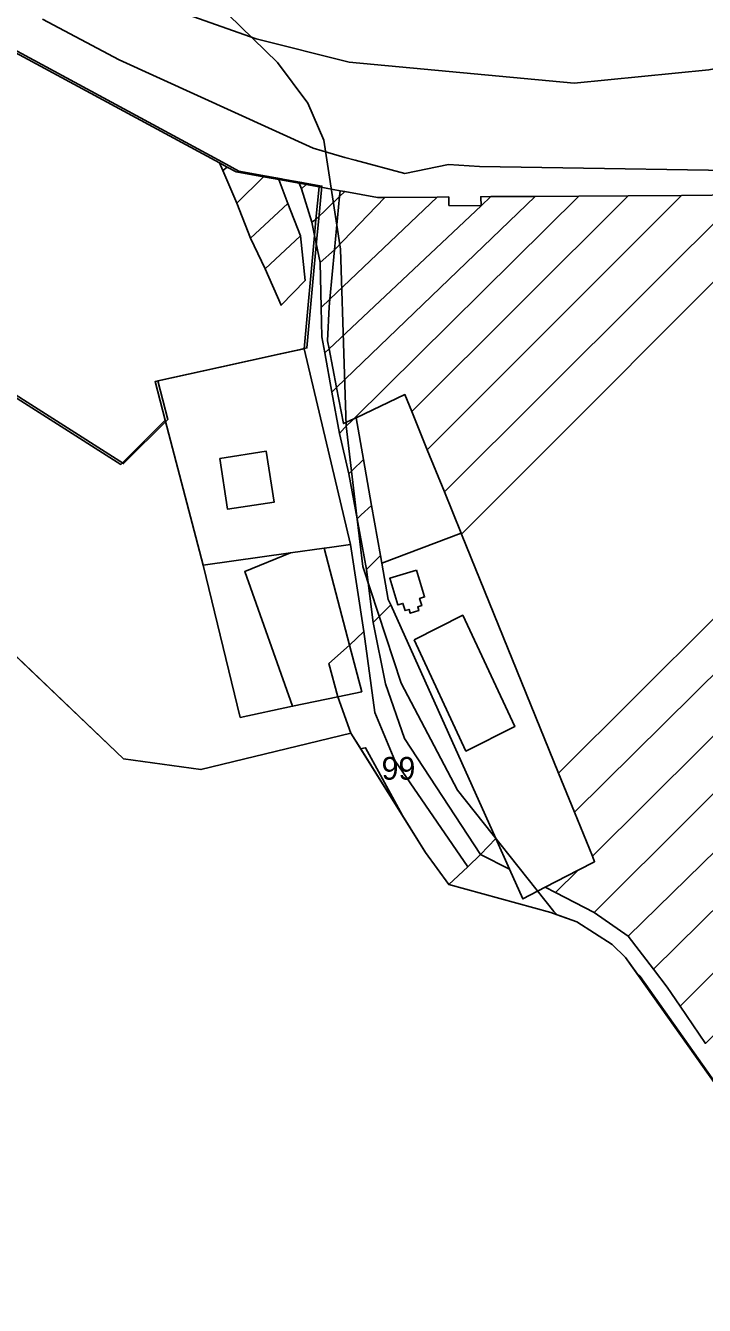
# Model space of a CAD drawing. Extents: x -535894 to -532834, y -1165802 to -1163645.
# Drawn here: x -533412.1 to -533262.6, y -1165186.4 to -1164904.7 of the extents above; entities that cross this region are included whole.
import ezdxf

# ---------------------------------------------------------------- set-up
doc = ezdxf.new("R2010")
doc.units = 0
for name, color, linetype in [('95560013', 7, 'Continuous'), ('95590013', 7, 'Continuous'), ('95600013', 7, 'Continuous'), ('95610013', 7, 'Continuous'), ('95630013', 7, 'Continuous'), ('95640013', 7, 'Continuous'), ('95660013', 7, 'Continuous')]:
    doc.layers.add(name, color=color, linetype=linetype)

msp = doc.modelspace()

# ---------------------------------------------------------------- linework, layer by layer
at = {"layer": '95560013'}
for points in [[(-533149.26, -1164901.65), (-533141.88, -1164917.25), (-533157.58, -1164933.38), (-533260.52, -1165035.2), (-533294.68, -1165069.27), (-533316.06, -1165016.63), (-533241.31, -1164941.86), (-533238.5, -1164941.84), (-533229.28, -1164940.77)], [(-533111.26, -1164912.65), (-533109.04, -1164916.24), (-533107.52, -1164920.92), (-533157.09, -1164970.71), (-533286.88, -1165099.92), (-533295.36, -1165095.55), (-533290.36, -1165090.63), (-533286.76, -1165088.76), (-533287.25, -1165087.56), (-533191.02, -1164991.97), (-533162.21, -1164964.36), (-533147.66, -1164949.6)], [(-533157.58, -1164933.38), (-533152.84, -1164941.12), (-533291.2, -1165077.84), (-533294.68, -1165069.27), (-533260.52, -1165035.2)], [(-533342.95, -1164942.3), (-533341.8, -1164941.18), (-533334.55, -1164942.49), (-533332.94, -1164942.48), (-533344.05, -1164954.01)], [(-533342.83, -1164941), (-533341.8, -1164941.18), (-533342.95, -1164942.3)], [(-533267.6, -1164942.04), (-533254.19, -1164941.95), (-533319.84, -1165007.34), (-533323.61, -1164998.03)], [(-533254.19, -1164941.95), (-533241.31, -1164941.86), (-533316.06, -1165016.63), (-533316.16, -1165016.4), (-533319.84, -1165007.34)], [(-533152.84, -1164941.12), (-533147.66, -1164949.6), (-533162.21, -1164964.36), (-533191.02, -1164991.97), (-533287.25, -1165087.56), (-533291.2, -1165077.84)], [(-533321.4, -1164942.4), (-533318.89, -1164942.38), (-533318.86, -1164944.25), (-533311.76, -1164944.33), (-533345.25, -1164975.83), (-533345.58, -1164974.08), (-533345.23, -1164966.6), (-533345.07, -1164964.92)], [(-533309.61, -1164942.31), (-533299.86, -1164942.25), (-533343.59, -1164984.36), (-533345.25, -1164975.83), (-533311.76, -1164944.33)], [(-533332.94, -1164942.48), (-533321.4, -1164942.4), (-533345.07, -1164964.92), (-533344.05, -1164954.01)], [(-533299.86, -1164942.25), (-533290.22, -1164942.19), (-533339.81, -1164991.22), (-533342.06, -1164992.28), (-533343.59, -1164984.36)], [(-533290.22, -1164942.19), (-533279.34, -1164942.12), (-533327.03, -1164989.6), (-533328.55, -1164985.88), (-533339.3, -1164990.98), (-533339.81, -1164991.22)], [(-533279.34, -1164942.12), (-533267.6, -1164942.04), (-533323.61, -1164998.03), (-533327.03, -1164989.6)], [(-533311.84, -1164942.33), (-533309.61, -1164942.31), (-533311.76, -1164944.33)], [(-533157.09, -1164970.71), (-533151.05, -1164978.13), (-533156.74, -1164983.77), (-533204.88, -1165032.37), (-533279.36, -1165105.17), (-533286.88, -1165099.92)], [(-533156.74, -1164983.77), (-533149.64, -1164990.09), (-533273.82, -1165112.38), (-533279.36, -1165105.17), (-533204.88, -1165032.37)], [(-533327.03, -1164989.6), (-533323.61, -1164998.03), (-533319.84, -1165007.34), (-533316.16, -1165016.4), (-533333.62, -1165022.99), (-533333.91, -1165021.36), (-533335.87, -1165010.29), (-533337.66, -1165000.19), (-533339.3, -1164990.98), (-533328.55, -1164985.88)], [(-533149.64, -1164990.09), (-533146.17, -1164986.67), (-533140.53, -1164993.73), (-533146.54, -1164999.72), (-533267.92, -1165120.55), (-533270.77, -1165116.36), (-533273.82, -1165112.38)], [(-533140.42, -1165007.98), (-533262.35, -1165128.75), (-533267.92, -1165120.55), (-533146.54, -1164999.72)], [(-533353.73, -1165020.77), (-533346.35, -1165019.74), (-533340.73, -1165041.06), (-533345.32, -1165045.1), (-533343.29, -1165052.42), (-533353.28, -1165054.53), (-533363.82, -1165024.85)], [(-533345.15, -1165019.57), (-533340.49, -1165018.91), (-533337.57, -1165038.08), (-533340.73, -1165041.06), (-533346.35, -1165019.74)], [(-533345.32, -1165045.1), (-533340.73, -1165041.06), (-533338.04, -1165051.31), (-533343.29, -1165052.42)], [(-533290.36, -1165090.63), (-533295.36, -1165095.55), (-533297.64, -1165094.39)]]:
    msp.add_lwpolyline(points, close=True, dxfattribs=at)
at = {"layer": '95590013'}
msp.add_lwpolyline([(-533372.98, -1165023.48), (-533353.73, -1165020.77), (-533363.82, -1165024.85), (-533353.28, -1165054.53), (-533364.81, -1165056.97)], close=True, dxfattribs=at)
at = {"layer": '95600013'}
msp.add_lwpolyline([(-533670.19, -1164839.35), (-533626.96, -1164831.3), (-533613.25, -1164834.55), (-533603.37, -1164835.56), (-533596.46, -1164833.25), (-533553.28, -1164851.89), (-533522.7, -1164887.69), (-533497.72, -1164933.47), (-533391.12, -1165001.26), (-533381.33, -1164991.55), (-533372.98, -1165023.48), (-533364.81, -1165056.97), (-533353.28, -1165054.53), (-533343.29, -1165052.42), (-533340.42, -1165060.46), (-533373.45, -1165068.48), (-533390.5, -1165066.09), (-533436.96, -1165021.83), (-533455.65, -1165016.42), (-533510.43, -1165042.58), (-533561.35, -1165072.56), (-533561.52, -1165072.67), (-533570, -1165063.27), (-533737.9, -1164874.36)], dxfattribs=at)
at = {"layer": '95610013'}
for points in [[(-533350.73, -1164975.81), (-533340.49, -1165018.91), (-533345.15, -1165019.57), (-533346.35, -1165019.74), (-533353.73, -1165020.77), (-533372.98, -1165023.48), (-533381.33, -1164991.55), (-533383.55, -1164983.05), (-533369.51, -1164979.95), (-533356.25, -1164977.03), (-533352.5, -1164976.21)], [(-533369.3, -1164999.94), (-533367.61, -1165011.14), (-533357.35, -1165009.59), (-533359.07, -1164998.38)]]:
    msp.add_lwpolyline(points, close=True, dxfattribs=at)
at = {"layer": '95630013'}
msp.add_lwpolyline([(-533192.2, -1164894.47), (-533236.41, -1164909.7), (-533261.61, -1164914.36), (-533291.28, -1164917.31), (-533340.78, -1164912.67), (-533361.33, -1164907.54), (-533389.23, -1164897.67)], dxfattribs=at)
at = {"layer": '95640013'}
for points in [[(-533427.21, -1164903.65), (-533369.34, -1164934.9), (-533368.62, -1164936.59), (-533365.53, -1164943.74), (-533362.54, -1164951.44), (-533359.28, -1164958.21), (-533355.82, -1164966.23), (-533350.5, -1164960.74), (-533351.5, -1164950.92), (-533354.34, -1164943.84), (-533356.31, -1164938.57), (-533351.86, -1164939.38), (-533351.34, -1164940.58), (-533349.07, -1164947.93), (-533348.45, -1164950.88), (-533350.73, -1164975.81), (-533352.5, -1164976.21), (-533356.25, -1164977.03), (-533369.51, -1164979.95), (-533383.55, -1164983.05), (-533381.33, -1164991.55), (-533391.12, -1165001.26), (-533497.72, -1164933.47), (-533454.32, -1164892.58)], [(-533408.38, -1164903.25), (-533391.45, -1164912.18), (-533348.75, -1164931.67), (-533346.78, -1164932.24), (-533341.76, -1164933.66), (-533339.52, -1164934.29), (-533328.53, -1164937.19), (-533318.96, -1164935.26), (-533312.12, -1164935.66), (-533238.8, -1164936.84), (-533230.7, -1164935.9), (-533147.32, -1164895.13)], [(-533147.32, -1164895.13), (-533230.7, -1164935.9), (-533238.8, -1164936.84), (-533312.12, -1164935.66), (-533318.96, -1164935.26), (-533328.53, -1164937.19), (-533339.52, -1164934.29), (-533341.76, -1164933.66), (-533346.78, -1164932.24), (-533348.75, -1164931.67), (-533391.45, -1164912.18), (-533408.38, -1164903.25)], [(-533389.23, -1164897.67), (-533361.33, -1164907.54), (-533340.78, -1164912.67), (-533291.28, -1164917.31), (-533261.61, -1164914.36), (-533236.41, -1164909.7), (-533192.2, -1164894.47)], [(-533254.19, -1164941.95), (-533267.6, -1164942.04), (-533279.34, -1164942.12), (-533290.22, -1164942.19), (-533299.86, -1164942.25), (-533309.61, -1164942.31), (-533311.84, -1164942.33), (-533311.76, -1164944.33), (-533318.86, -1164944.25), (-533318.89, -1164942.38), (-533321.4, -1164942.4), (-533332.94, -1164942.48), (-533334.55, -1164942.49), (-533341.8, -1164941.18), (-533342.83, -1164941), (-533347.43, -1164940.17), (-533350.31, -1164939.66), (-533351.86, -1164939.38), (-533356.31, -1164938.57), (-533359.67, -1164937.97), (-533365.69, -1164936.87), (-533367.68, -1164935.8), (-533369.34, -1164934.9), (-533427.21, -1164903.65)], [(-533252.35, -1165148.73), (-533279.97, -1165109.85), (-533282.89, -1165106.98), (-533290.68, -1165102.01), (-533296.36, -1165099.92), (-533318.84, -1165093.8), (-533314.71, -1165089.88), (-533311.86, -1165087.17), (-533305.48, -1165090.39), (-533302.55, -1165096.94), (-533297.64, -1165094.39), (-533295.36, -1165095.55), (-533286.88, -1165099.92), (-533279.36, -1165105.17), (-533273.82, -1165112.38), (-533270.77, -1165116.36), (-533267.92, -1165120.55), (-533262.35, -1165128.75)]]:
    msp.add_lwpolyline(points, dxfattribs=at)
for points in [[(-533367.68, -1164935.8), (-533368.62, -1164936.59), (-533369.34, -1164934.9)], [(-533368.62, -1164936.59), (-533367.68, -1164935.8), (-533365.69, -1164936.87), (-533359.67, -1164937.97), (-533365.53, -1164943.74)], [(-533359.67, -1164937.97), (-533356.31, -1164938.57), (-533354.34, -1164943.84), (-533362.54, -1164951.44), (-533365.53, -1164943.74)], [(-533351.86, -1164939.38), (-533350.31, -1164939.66), (-533351.34, -1164940.58)], [(-533350.31, -1164939.66), (-533347.43, -1164940.17), (-533348.12, -1164947.33), (-533349.07, -1164947.93), (-533351.34, -1164940.58)], [(-533347.43, -1164940.17), (-533342.83, -1164941), (-533342.95, -1164942.3), (-533348.12, -1164947.33)], [(-533354.34, -1164943.84), (-533351.5, -1164950.92), (-533359.28, -1164958.21), (-533362.54, -1164951.44)], [(-533348.12, -1164947.33), (-533342.95, -1164942.3), (-533344.05, -1164954.01), (-533347.18, -1164956.81), (-533348.45, -1164950.88)], [(-533349.07, -1164947.93), (-533348.12, -1164947.33), (-533348.45, -1164950.88)], [(-533359.28, -1164958.21), (-533351.5, -1164950.92), (-533350.5, -1164960.74), (-533355.82, -1164966.23)], [(-533347.18, -1164956.81), (-533346.96, -1164966.72), (-533346.81, -1164973.18), (-533346.18, -1164976.7), (-533344.61, -1164985.36), (-533342.97, -1164994.5), (-533340.92, -1165003.34), (-533339.05, -1165013.22), (-533337.02, -1165024.42), (-533335.51, -1165036.11), (-533332.78, -1165049.58), (-533328.63, -1165061.62), (-533311.86, -1165087.17), (-533314.71, -1165089.88), (-533330.78, -1165066.5), (-533335.17, -1165055.93), (-533337.57, -1165038.08), (-533340.49, -1165018.91), (-533350.73, -1164975.81), (-533348.45, -1164950.88)], [(-533347.18, -1164956.81), (-533344.05, -1164954.01), (-533345.07, -1164964.92), (-533346.96, -1164966.72)], [(-533345.07, -1164964.92), (-533345.23, -1164966.6), (-533345.58, -1164974.08), (-533345.25, -1164975.83), (-533346.18, -1164976.7), (-533346.81, -1164973.18), (-533346.96, -1164966.72)], [(-533346.18, -1164976.7), (-533345.25, -1164975.83), (-533343.59, -1164984.36), (-533344.61, -1164985.36)], [(-533344.61, -1164985.36), (-533343.59, -1164984.36), (-533342.06, -1164992.28), (-533339.81, -1164991.22), (-533341.87, -1164993.25), (-533342.97, -1164994.5)], [(-533339.3, -1164990.98), (-533337.66, -1165000.19), (-533340.08, -1165002.52), (-533340.92, -1165003.34), (-533342.97, -1164994.5), (-533341.87, -1164993.25), (-533339.81, -1164991.22)], [(-533369.3, -1164999.94), (-533359.07, -1164998.38), (-533357.35, -1165009.59), (-533367.61, -1165011.14)], [(-533340.08, -1165002.52), (-533337.66, -1165000.19), (-533335.87, -1165010.29), (-533338.16, -1165012.4), (-533339.05, -1165013.22), (-533340.92, -1165003.34)], [(-533338.16, -1165012.4), (-533335.87, -1165010.29), (-533333.91, -1165021.36), (-533336.02, -1165023.46), (-533337.02, -1165024.42), (-533339.05, -1165013.22)], [(-533316.06, -1165016.63), (-533294.68, -1165069.27), (-533291.2, -1165077.84), (-533287.25, -1165087.56), (-533286.76, -1165088.76), (-533290.36, -1165090.63), (-533297.64, -1165094.39), (-533302.55, -1165096.94), (-533305.48, -1165090.39), (-533308.51, -1165083.67), (-533331.65, -1165032.22), (-533332.19, -1165031.01), (-533333.62, -1165022.99), (-533316.16, -1165016.4)], [(-533333.62, -1165022.99), (-533332.19, -1165031.01), (-533331.65, -1165032.22), (-533333.89, -1165034.46), (-533335.51, -1165036.11), (-533337.02, -1165024.42), (-533336.02, -1165023.46), (-533333.91, -1165021.36)], [(-533325.97, -1165024.54), (-533324.22, -1165030.44), (-533325.31, -1165030.77), (-533324.83, -1165032.37), (-533325.72, -1165032.63), (-533325.47, -1165033.45), (-533327.35, -1165034.03), (-533327.6, -1165033.2), (-533328.48, -1165033.47), (-533328.97, -1165031.89), (-533330.07, -1165032.22), (-533331.86, -1165026.33)], [(-533325.97, -1165024.54), (-533331.86, -1165026.33), (-533330.07, -1165032.22), (-533328.97, -1165031.89), (-533328.48, -1165033.47), (-533327.6, -1165033.2), (-533327.35, -1165034.03), (-533325.47, -1165033.45), (-533325.72, -1165032.63), (-533324.83, -1165032.37), (-533325.31, -1165030.77), (-533324.22, -1165030.44)], [(-533333.89, -1165034.46), (-533331.65, -1165032.22), (-533308.51, -1165083.67), (-533311.86, -1165087.17), (-533328.63, -1165061.62), (-533332.78, -1165049.58), (-533335.51, -1165036.11)], [(-533326.51, -1165039.93), (-533315.1, -1165064.39), (-533304.34, -1165059.01), (-533315.79, -1165034.5)], [(-533326.51, -1165039.93), (-533315.79, -1165034.5), (-533304.34, -1165059.01), (-533315.1, -1165064.39)], [(-533337.57, -1165038.08), (-533335.17, -1165055.93), (-533330.78, -1165066.5), (-533314.71, -1165089.88), (-533318.84, -1165093.8), (-533324, -1165086.69), (-533340.42, -1165060.46), (-533343.29, -1165052.42), (-533338.04, -1165051.31), (-533340.73, -1165041.06)], [(-533311.86, -1165087.17), (-533308.51, -1165083.67), (-533305.48, -1165090.39)]]:
    msp.add_lwpolyline(points, close=True, dxfattribs=at)
at = {"layer": '95660013'}
for points in [[(-533522.095, -1164887.508), (-533497.114, -1164933.287), (-533390.513, -1165001.084), (-533380.721, -1164991.378), (-533382.945, -1164982.87), (-533368.897, -1164979.776), (-533355.644, -1164976.854), (-533351.891, -1164976.035), (-533350.116, -1164975.638), (-533348.56, -1164958.614), (-533347.837, -1164950.711), (-533347.512, -1164947.155), (-533346.817, -1164939.999), (-533349.698, -1164939.487), (-533351.256, -1164939.202), (-533355.068, -1164938.512), (-533355.703, -1164938.397), (-533359.057, -1164937.792), (-533365.083, -1164936.699), (-533368.736, -1164934.723), (-533382.308, -1164927.394), (-533426.603, -1164903.475)], [(-533426.603, -1164903.475), (-533382.308, -1164927.394), (-533368.736, -1164934.723), (-533365.083, -1164936.699), (-533359.057, -1164937.792), (-533355.703, -1164938.397), (-533355.068, -1164938.512), (-533351.256, -1164939.202), (-533349.698, -1164939.487), (-533346.817, -1164939.999), (-533347.512, -1164947.155), (-533347.837, -1164950.711), (-533348.56, -1164958.614), (-533350.116, -1164975.638), (-533351.891, -1164976.035), (-533355.644, -1164976.854), (-533368.897, -1164979.776), (-533382.945, -1164982.87), (-533380.721, -1164991.378), (-533390.513, -1165001.084), (-533497.114, -1164933.287), (-533522.095, -1164887.508)], [(-533367.42, -1164902.28), (-533356.59, -1164912.8), (-533349.9, -1164921.72), (-533346.4, -1164929.841), (-533342.74, -1164953.89), (-533341.908, -1164979.159), (-533341.46, -1164992.76), (-533339.243, -1165011.507), (-533337.792, -1165023.782), (-533329.361, -1165049.46), (-533316.93, -1165073.03), (-533295.745, -1165099.748), (-533294.968, -1165100.432), (-533296.36, -1165099.92), (-533318.84, -1165093.8), (-533324, -1165086.69), (-533329.073, -1165078.587), (-533333.905, -1165069.717), (-533333.909, -1165069.71), (-533337.21, -1165063.65), (-533337.643, -1165063.747), (-533338.274, -1165063.889), (-533340.42, -1165060.46), (-533373.45, -1165068.48), (-533390.5, -1165066.09), (-533425.693, -1165032.564)], [(-533245.64, -1165157.93), (-533276.71, -1165113.99), (-533277.344, -1165113.547), (-533279.97, -1165109.85), (-533282.89, -1165106.98), (-533290.68, -1165102.01), (-533294.968, -1165100.432), (-533295.745, -1165099.748), (-533316.93, -1165073.03), (-533329.361, -1165049.46), (-533337.792, -1165023.782), (-533339.243, -1165011.507), (-533341.46, -1164992.76), (-533341.908, -1164979.159), (-533342.74, -1164953.89), (-533346.4, -1164929.841), (-533349.9, -1164921.72), (-533356.59, -1164912.8), (-533367.42, -1164902.28)]]:
    msp.add_lwpolyline(points, dxfattribs=at)
for points in [[(-533333.905, -1165069.717), (-533329.073, -1165078.587), (-533338.274, -1165063.889), (-533337.643, -1165063.747), (-533337.21, -1165063.65), (-533333.909, -1165069.71)], [(-533230.475, -1165183.857), (-533229.131, -1165186.444), (-533233.16, -1165181.49), (-533239.66, -1165168.21), (-533252.35, -1165148.73), (-533277.344, -1165113.547), (-533276.71, -1165113.99), (-533245.64, -1165157.93), (-533236.776, -1165172.663), (-533233.21, -1165178.59)]]:
    msp.add_lwpolyline(points, close=True, dxfattribs=at)

# ---------------------------------------------------------------- texts
msp.add_text('99', height=5, rotation=360, dxfattribs=at).set_placement((-533333.674, -1165070.69))

doc.saveas('drawing.dxf')
